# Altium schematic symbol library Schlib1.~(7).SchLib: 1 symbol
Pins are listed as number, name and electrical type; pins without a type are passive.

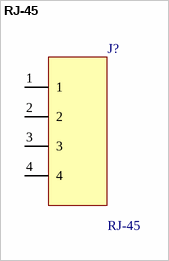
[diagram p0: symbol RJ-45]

## RJ-45
designator J?
footprint PCBComponent_1
pins: 1, 2, 3, 4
